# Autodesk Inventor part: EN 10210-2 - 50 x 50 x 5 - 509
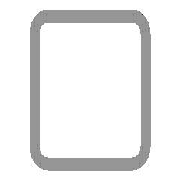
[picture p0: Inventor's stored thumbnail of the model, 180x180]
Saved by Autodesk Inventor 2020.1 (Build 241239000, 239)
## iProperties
IsCustomPart: 1
_CCFamilyMember: 16
_CCFamilyDisplayName: DIN EN 10210-2 (USAS B17.1 quadratisch) - Rohrleitung — In Klammern angegebene Größen wurden aufgehoben
_FrameMemberDoc: Frame Member File
_Version: 15.0.0
_GetPNFromCC: 1
Created: 2019-01
Part Number: EN 10210-2 - 50 x 50 x 5 - 509
Material: Stahl, weich
Description: Rohrleitung
Document SubType Name: Modeling
Standard: DIN
Designer: lutzd
Standard Revision: 2006-07
Standards Organization: DIN
Language: de-DE
Size Designation: 50 x 50 x 5
Categories: <MemberInstance><Categories><Category DisplayName="Profile" InternalName="089c4875-fa83-4c05-b084-43b9cc11f5ed" Mnemonic="GRDR"><CategoryParameter DisplayName="
Stock Number: 50 x 50 x 5
Mass: 3488.9 g
Surface Area: 1740.63 cm^2
Volume: 444.446 cm^3
Density: 7.85 g/cm^3
Appearance: Halbpoliert
G_W: 50,000 mm
G_H: 50,000 mm
DocNumber: ADSK-014202
Folder: .
Dimensions: 50x50x509 mm
Mass: 3,489 kg
+359A702E-C945-4D6A-87FE-D4FA9655738C+SCHNITTDETAIL1: Schnittwinkel 90,00 grd
G_L: 509,000 mm
Title: Profil-Bauteil
Author: lutzd
Revision Number: -
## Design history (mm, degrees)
node "Startebene"
node "Endebene"
sketch "Skizze"
  geometry: L1 (-25, -17.5)-(-25, 17.5); L2 (-17.5, 25)-(17.5, 25); L3 (25, 17.5)-(25, -17.5); L4 (17.5, -25)-(-17.5, -25); L5 (-15, 20)-(15, 20); L6 (20, 15)-(20, -15); L7 (15, -20)-(-15, -20); L8 (-20, -15)-(-20, 15); L9 (0, 37.175)-(0, -37.175) reference; L10 (-37.175, 0)-(37.175, 0) reference; A1 r 7.5 centre (-17.5, -17.5) between (-25, -17.5) and (-17.5, -25); A2 r 7.5 centre (-17.5, 17.5) between (-17.5, 25) and (-25, 17.5); A3 r 7.5 centre (17.5, 17.5) between (25, 17.5) and (17.5, 25); A4 r 7.5 centre (17.5, -17.5) between (17.5, -25) and (25, -17.5); A5 r 5 centre (-15, -15) between (-20, -15) and (-15, -20); A6 r 5 centre (-15, 15) between (-15, 20) and (-20, 15); A7 r 5 centre (15, 15) between (20, 15) and (15, 20); A8 r 5 centre (15, -15) between (15, -20) and (20, -15)
  constraints: 16 end point, 16 point on circle, 16 tangent, 8 centre point, 6 equal radius, 4 parallel, 2 perpendicular, 2 other
  dimensions: "d7" = 7.5 radius of A1 (= G_IR); "d10" = 50 distance between parallel lines of L2 L4 (= G_H); "d11" = 50 distance between parallel lines of L1 L3 (= G_W); "d12" = 5 distance between parallel lines of L3 L6 (= G_T); "d15" = 25 distance between parallel lines of L2 L10 (= 0.5 x d10); "d16" = 25 distance between parallel lines of L9 L3 (= 0.5 x d11); "d19" = 5 radius of A5 (= G_T); "d20" = 5 distance between parallel lines of L4 L7 (= G_T)
extrude "Körper" new body sketch "Skizze" stored distance "d3" = 509 (= G_L); taper "d4" = 0 deg
node "Driven Length"
  sketch "Sketch3"
    geometry: L1 (0, 0)-(10, 0) reference
    constraints: 2 end point, 1 horizontal
  workplane "Work Plane3"
  sketch "Sketch4"
    geometry: L1 (-2, 0)-(12, 0) reference; L2 (-2, 509)-(12, 509) reference
    dimensions: "d18" = 509 distance between parallel lines of L1 L2 (derived)
workplane "Arbeitsebene4"
feature "Trennen1"
body "Solid1"
other parameters: "G_W" = 50 [user parameter; used in 1 equation term], "G_H" = 50 [user parameter; used in 1 equation term], "G_T" = 5 [user parameter; used in 3 equation terms], "G_IR" = 7.5 [user parameter; used in 1 equation term], "G_L" = 509 (= d18) [user parameter; used in 1 equation term], "G_OFFSET_START" = 0 [user parameter; used in 1 equation term], "d13" = 0 (computed from G_OFFSET_START), "d14" = 509 (= G_OFFSET_END + B_L), "B_L" = 559 [user parameter; used in 1 equation term], "d17" = 90 deg
